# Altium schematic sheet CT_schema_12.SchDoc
size 145 x 119 mm
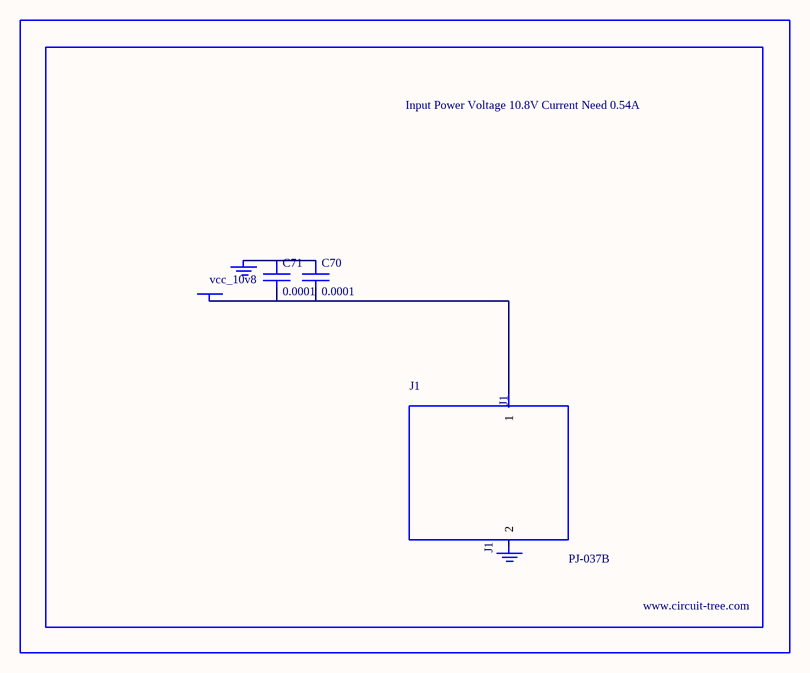
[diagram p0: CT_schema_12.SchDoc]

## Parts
BORDER11  (no value)
C70  0.0001  [EXV-9H]
C71  0.0001  [EXV-9H]
GND_INSTANCE_11_0  (no value)
GND_INSTANCE_11_1  (no value)
J1  PJ-037B  [PJ-037B_PACKAGE]
POWER_INSTANCE_11_0  vcc_10v8

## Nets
NetC70_1: C70.1 C71.1 GND_INSTANCE_11_0.0(GND)
NetC70_2: C70.2 C71.2 J1.1 POWER_INSTANCE_11_0.0(PWR)

Not connected (* = marked no-connect by the designer): GND_INSTANCE_11_1 0(GND); J1 2

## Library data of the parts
BORDER11 = BORDER_PAGE11
C70 C71 = EDK107M035A9HAA
GND_INSTANCE_11_0 GND_INSTANCE_11_1 = GND
POWER_INSTANCE_11_0 = PWR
